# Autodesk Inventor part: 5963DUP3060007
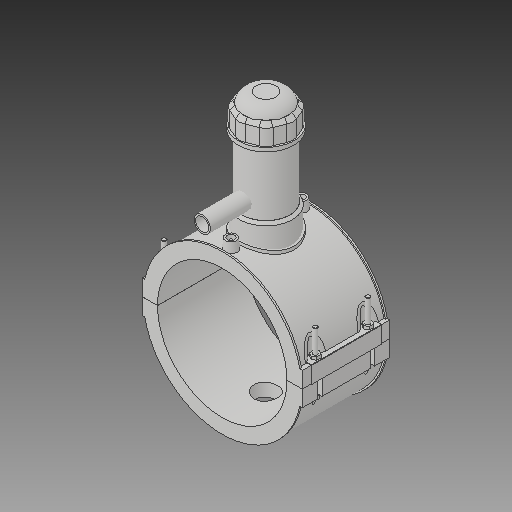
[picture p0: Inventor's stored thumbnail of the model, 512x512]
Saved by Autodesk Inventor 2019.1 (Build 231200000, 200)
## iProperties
Created: 2017-07
Part Number: 5963DUP3060007
Material: Generic
Description: PLASSON TAPPING SADDLE 6''DIPS x 3/4''CTS
Document SubType Name: Modeling
Designer: KIM
Density: 1 g/cm^3
Appearance: Default
Author: KIM
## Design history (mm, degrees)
derived "5963DBP_5963BUP.ipt"
feature "Solid1::5963DBP_5963BUP.ipt"
feature "Solid2::5963DBP_5963BUP.ipt"
feature "Solid3::5963DBP_5963BUP.ipt"
tag "TaggingFeature1"
body "Solid1"
body "Solid2"
body "Solid3"
other parameters: "d0" = 174.5, "d2" = 215.9, "d3" = 43.625, "d4" = 118.11, "d5" = 0, "d6" = 0.1, "d8" = 0, "d19" = 6, "d20" = 6, "d21" = 70.866, "d23" = 0, "d24" = 35.433, "d26" = 0, "d27" = 3, "d28" = 3, "d29" = 3, "d30" = 58.16667, "d31" = 6, "d32" = 0, "d33" = 0, "d34" = 0.6, "d40" = 108.888, "d41" = 75.035, "d43" = 0, "d45" = 0, "d47" = 175.566, "d70" = 15, "d72" = 0, "d73" = 6, "d75" = 5, "d76" = 0, "d77" = 8.725, "d78" = 117.25, "d79" = 15, "d80" = 47.244, "d82" = 5 deg, "d84" = 4, "d85" = 14, "d86" = 0, "d87" = 3, "d88" = 0, "d89" = 1, "d90" = 1, "d91" = 94.488, "d92" = 0, "d93" = 0.5, "d94" = 91.84211, "d96" = 213.588, "d97" = 2.3622, "d98" = 0, "d120" = 140 deg, "d121" = 24.228, "d122" = 20 deg, "d123" = 418.8, "d124" = 125.64, "d126" = 0, "d143" = 179.735, "d145" = 26.84615, "d149" = 2.6175, "d150" = 29.53077, "d153" = 118.11, "d154" = 0, "d156" = 104.7, "d157" = 160 deg, "d159" = 6.98, "d161" = 2.6175, "d162" = 70.866, "d163" = 0, "d164" = 87.25, "d167" = 17.45, "d168" = 102.14634, "d170" = 3.4335, "d172" = 0, "d173" = 1, "d175" = 87.25, "d176" = 20 deg, "d177" = 12.215, "d178" = 34.9, "d180" = 0, "d183" = 13.96, "d184" = 9.772, "d185" = 38.38575, "d186" = 38.38575, "d187" = 104.7, "d188" = 10.47, "d189" = 12.215, "d190" = 0, "d191" = 157.05, "d193" = 7.3248, "d194" = 4.13385, "d195" = 90 deg, "d197" = 0, "d199" = 0, "d200" = 17.45, "d202" = 0, "d203" = 177.038, "d204" = 71.28325, "d205" = 52.5245, "d206" = 63.77975, "d207" = 132.7785, "d208" = 138.08964, "d209" = 164.64534, "d210" = 64.5301, "d211" = 75.035, "d212" = 60.028, "d213" = 48.5766, "d216" = 0, "d217" = 17.45, "d218" = 17.45, "d219" = 3.49, "d222" = 174.5, "d224" = 0, "d225" = 65.024, "d226" = 22.1, "d227" = 17.68, "d228" = 86.106, "d230" = 5.235, "d_" = 174.5, "B_" = 215.9, "L_" = 118.11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
